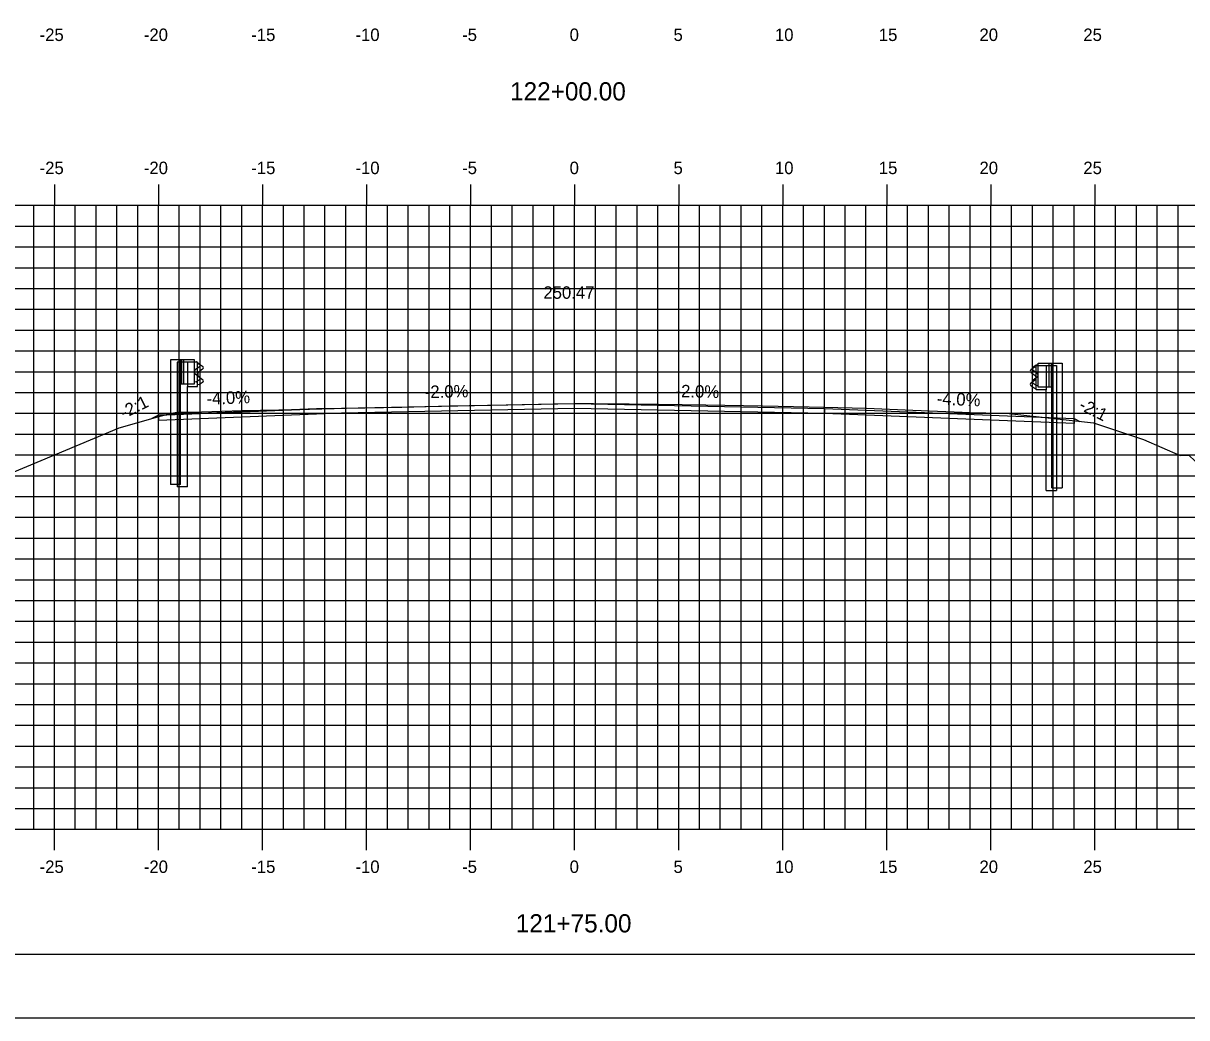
# Model space of a CAD drawing. Extents: x -22 to 1480, y -1511 to 8.
# Drawn here: x 1270.4 to 1326.4, y -1511.4 to -1463.6 of the extents above; entities that cross this region are included whole.
import ezdxf

# ---------------------------------------------------------------- set-up
doc = ezdxf.new("R2010")
doc.units = 0
for name, color, linetype in [('ANNOTATION', 7, 'Continuous'), ('BORDER', 7, 'Continuous'), ('D_Guardrail_Beam_Lt', 7, 'Continuous'), ('D_Guardrail_Beam_Rt', 7, 'Continuous'), ('D_Roadway_Centerline', 7, 'Continuous'), ('D_Roadway_Centerline_Text', 7, 'Continuous'), ('D_Roadway_Edge_Shoulder', 7, 'Continuous'), ('D_Roadway_Edge_TW', 7, 'Continuous'), ('D_Roadway_SlopeLines', 7, 'Continuous'), ('H_V ANNOTATION', 7, 'Continuous'), ('MAJOR', 7, 'Continuous'), ('MINOR', 7, 'Continuous'), ('PLOT BOUNDARY', 7, 'Continuous'), ('S_Guardrail_Beam', 7, 'Continuous'), ('S_Roadway_Centerline', 7, 'Continuous')]:
    doc.layers.add(name, color=color, linetype=linetype)

msp = doc.modelspace()

# ---------------------------------------------------------------- linework, layer by layer
at = {"layer": 'BORDER'}
msp.add_line((1221.939, -1508.331), (1381.939, -1508.331), dxfattribs=at)
at = {"layer": 'D_Guardrail_Beam_Lt'}
for p, q in [((1277.51, -1479.754), (1277.51, -1485.754)), ((1277.981, -1479.754), (1277.51, -1479.754)), ((1278.668, -1479.754), (1277.981, -1479.754)), ((1277.981, -1479.754), (1277.981, -1480.921)), ((1278.043, -1479.754), (1278.043, -1480.921)), ((1278.147, -1479.754), (1278.147, -1480.921)), ((1278.668, -1480.921), (1278.668, -1479.754)), ((1278.668, -1479.837), (1278.742, -1479.852)), ((1278.758, -1479.858), (1278.902, -1479.958)), ((1278.673, -1480.302), (1278.673, -1480.372)), ((1278.902, -1480.102), (1278.706, -1480.238)), ((1278.706, -1480.437), (1278.902, -1480.573)), ((1277.981, -1480.921), (1278.668, -1480.921)), ((1278.002, -1485.754), (1278.002, -1480.921)), ((1278.742, -1480.823), (1278.668, -1480.837)), ((1278.902, -1480.716), (1278.758, -1480.816)), ((1278.002, -1485.754), (1277.51, -1485.754))]:
    msp.add_line(p, q, dxfattribs=at)
for centre, major_axis, start_param, end_param in [((1278.734, -1479.892), (0.0417, 0), 0.959931, 1.376053), ((1278.851, -1480.03), (0.0877, 0), 5.323254, 7.243116), ((1278.752, -1480.302), (-0.0789, 0), 5.323254, 6.283185), ((1278.752, -1480.372), (-0.0789, 0), 6.283185, 7.243116), ((1278.851, -1480.644), (0.0877, 0), 5.323254, 7.243116), ((1278.734, -1480.782), (0.0417, 0), 4.907132, 5.323254)]:
    msp.add_ellipse(centre, major_axis=major_axis, ratio=0.995501, start_param=start_param, end_param=end_param, dxfattribs=at)
at = {"layer": 'D_Guardrail_Beam_Rt'}
for p, q in [((1319.12, -1480.018), (1318.977, -1480.118)), ((1319.21, -1479.997), (1319.136, -1480.012)), ((1319.21, -1479.914), (1319.897, -1479.914)), ((1319.21, -1481.081), (1319.21, -1479.914)), ((1319.731, -1479.914), (1319.731, -1481.081)), ((1319.835, -1479.914), (1319.835, -1481.081)), ((1319.897, -1479.914), (1320.368, -1479.914)), ((1319.897, -1479.914), (1319.897, -1481.081)), ((1320.368, -1479.914), (1320.368, -1485.914)), ((1318.977, -1480.262), (1319.172, -1480.398)), ((1319.172, -1480.597), (1318.977, -1480.733)), ((1319.206, -1480.462), (1319.206, -1480.532)), ((1318.977, -1480.876), (1319.12, -1480.976)), ((1319.136, -1480.983), (1319.21, -1480.997)), ((1319.897, -1481.081), (1319.21, -1481.081)), ((1319.877, -1485.914), (1319.877, -1481.081)), ((1319.877, -1485.914), (1320.368, -1485.914))]:
    msp.add_line(p, q, dxfattribs=at)
for centre, major_axis, start_param, end_param in [((1319.144, -1480.052), (-0.0417, 0), 4.907132, 5.323254), ((1319.027, -1480.19), (-0.0877, 0), 5.323254, 7.243116), ((1319.127, -1480.462), (0.0789, 0), 0, 0.959931), ((1319.127, -1480.532), (0.0789, 0), 5.323254, 6.283185), ((1319.027, -1480.804), (-0.0877, 0), 5.323254, 7.243116), ((1319.144, -1480.942), (-0.0417, 0), 0.959931, 1.376053)]:
    msp.add_ellipse(centre, major_axis=major_axis, ratio=0.995501, start_param=start_param, end_param=end_param, dxfattribs=at)
at = {"layer": 'D_Roadway_Centerline'}
msp.add_lwpolyline([(1276.623, -1482.575), (1276.939, -1482.417), (1278.939, -1482.337), (1284.939, -1482.097), (1296.939, -1481.857), (1308.939, -1482.097), (1318.939, -1482.497), (1320.939, -1482.577), (1321.222, -1482.718)], dxfattribs=at)
at = {"layer": 'D_Roadway_Edge_Shoulder'}
for points in [[(1284.939, -1482.097), (1278.939, -1482.337), (1278.939, -1482.337), (1276.939, -1482.417), (1276.939, -1482.667), (1278.939, -1482.587), (1278.939, -1482.587), (1284.939, -1482.347)], [(1308.939, -1482.097), (1318.939, -1482.497), (1318.939, -1482.497), (1320.939, -1482.577), (1320.939, -1482.827), (1318.939, -1482.747), (1318.939, -1482.747), (1308.939, -1482.347)]]:
    msp.add_lwpolyline(points, close=True, dxfattribs=at)
at = {"layer": 'D_Roadway_Edge_TW'}
msp.add_lwpolyline([(1284.939, -1482.347), (1284.939, -1482.097), (1296.939, -1481.857), (1308.939, -1482.097), (1308.939, -1482.347), (1296.939, -1482.107)], close=True, dxfattribs=at)
at = {"layer": 'D_Roadway_SlopeLines'}
for points in [[(1276.939, -1482.417), (1276.623, -1482.575)], [(1320.939, -1482.577), (1321.222, -1482.718)]]:
    msp.add_lwpolyline(points, dxfattribs=at)
at = {"layer": 'MAJOR'}
for p, q in [((1271.939, -1471.329), (1271.939, -1472.331)), ((1276.939, -1471.329), (1276.939, -1472.331)), ((1281.939, -1471.329), (1281.939, -1472.331)), ((1286.939, -1471.329), (1286.939, -1472.331)), ((1291.939, -1471.329), (1291.939, -1472.331)), ((1296.939, -1471.329), (1296.939, -1472.331)), ((1301.939, -1471.329), (1301.939, -1472.331)), ((1306.939, -1471.329), (1306.939, -1472.331)), ((1311.939, -1471.329), (1311.939, -1472.331)), ((1316.939, -1471.329), (1316.939, -1472.331)), ((1321.939, -1471.329), (1321.939, -1472.331)), ((1226.939, -1472.331), (1366.939, -1472.331)), ((1226.939, -1472.331), (1366.939, -1472.331)), ((1271.939, -1502.331), (1271.939, -1472.331)), ((1276.939, -1502.331), (1276.939, -1472.331)), ((1281.939, -1502.331), (1281.939, -1472.331)), ((1286.939, -1502.331), (1286.939, -1472.331)), ((1291.939, -1502.331), (1291.939, -1472.331)), ((1296.939, -1502.331), (1296.939, -1472.331)), ((1301.939, -1502.331), (1301.939, -1472.331)), ((1306.939, -1502.331), (1306.939, -1472.331)), ((1311.939, -1502.331), (1311.939, -1472.331)), ((1316.939, -1502.331), (1316.939, -1472.331)), ((1321.939, -1502.331), (1321.939, -1472.331)), ((1226.939, -1477.331), (1366.939, -1477.331)), ((1226.939, -1482.331), (1366.939, -1482.331)), ((1226.939, -1487.331), (1366.939, -1487.331)), ((1226.939, -1492.331), (1366.939, -1492.331)), ((1226.939, -1497.331), (1366.939, -1497.331)), ((1226.939, -1502.331), (1366.939, -1502.331)), ((1226.939, -1502.331), (1366.939, -1502.331)), ((1271.939, -1503.333), (1271.939, -1502.331)), ((1276.939, -1503.333), (1276.939, -1502.331)), ((1281.939, -1503.333), (1281.939, -1502.331)), ((1286.939, -1503.333), (1286.939, -1502.331)), ((1291.939, -1503.333), (1291.939, -1502.331)), ((1296.939, -1503.333), (1296.939, -1502.331)), ((1301.939, -1503.333), (1301.939, -1502.331)), ((1306.939, -1503.333), (1306.939, -1502.331)), ((1311.939, -1503.333), (1311.939, -1502.331)), ((1316.939, -1503.333), (1316.939, -1502.331)), ((1321.939, -1503.333), (1321.939, -1502.331))]:
    msp.add_line(p, q, dxfattribs=at)
at = {"layer": 'MINOR'}
for p, q in [((1270.939, -1502.331), (1270.939, -1472.331)), ((1272.939, -1502.331), (1272.939, -1472.331)), ((1273.939, -1502.331), (1273.939, -1472.331)), ((1274.939, -1502.331), (1274.939, -1472.331)), ((1275.939, -1502.331), (1275.939, -1472.331)), ((1277.939, -1502.331), (1277.939, -1472.331)), ((1278.939, -1502.331), (1278.939, -1472.331)), ((1279.939, -1502.331), (1279.939, -1472.331)), ((1280.939, -1502.331), (1280.939, -1472.331)), ((1282.939, -1502.331), (1282.939, -1472.331)), ((1283.939, -1502.331), (1283.939, -1472.331)), ((1284.939, -1502.331), (1284.939, -1472.331)), ((1285.939, -1502.331), (1285.939, -1472.331)), ((1287.939, -1502.331), (1287.939, -1472.331)), ((1288.939, -1502.331), (1288.939, -1472.331)), ((1289.939, -1502.331), (1289.939, -1472.331)), ((1290.939, -1502.331), (1290.939, -1472.331)), ((1292.939, -1502.331), (1292.939, -1472.331)), ((1293.939, -1502.331), (1293.939, -1472.331)), ((1294.939, -1502.331), (1294.939, -1472.331)), ((1295.939, -1502.331), (1295.939, -1472.331)), ((1297.939, -1502.331), (1297.939, -1472.331)), ((1298.939, -1502.331), (1298.939, -1472.331)), ((1299.939, -1502.331), (1299.939, -1472.331)), ((1300.939, -1502.331), (1300.939, -1472.331)), ((1302.939, -1502.331), (1302.939, -1472.331)), ((1303.939, -1502.331), (1303.939, -1472.331)), ((1304.939, -1502.331), (1304.939, -1472.331)), ((1305.939, -1502.331), (1305.939, -1472.331)), ((1307.939, -1502.331), (1307.939, -1472.331)), ((1308.939, -1502.331), (1308.939, -1472.331)), ((1309.939, -1502.331), (1309.939, -1472.331)), ((1310.939, -1502.331), (1310.939, -1472.331)), ((1312.939, -1502.331), (1312.939, -1472.331)), ((1313.939, -1502.331), (1313.939, -1472.331)), ((1314.939, -1502.331), (1314.939, -1472.331)), ((1315.939, -1502.331), (1315.939, -1472.331)), ((1317.939, -1502.331), (1317.939, -1472.331)), ((1318.939, -1502.331), (1318.939, -1472.331)), ((1319.939, -1502.331), (1319.939, -1472.331)), ((1320.939, -1502.331), (1320.939, -1472.331)), ((1322.939, -1502.331), (1322.939, -1472.331)), ((1323.939, -1502.331), (1323.939, -1472.331)), ((1324.939, -1502.331), (1324.939, -1472.331)), ((1325.939, -1502.331), (1325.939, -1472.331)), ((1226.939, -1473.331), (1366.939, -1473.331)), ((1226.939, -1474.331), (1366.939, -1474.331)), ((1226.939, -1475.331), (1366.939, -1475.331)), ((1226.939, -1476.331), (1366.939, -1476.331)), ((1226.939, -1478.331), (1366.939, -1478.331)), ((1226.939, -1479.331), (1366.939, -1479.331)), ((1226.939, -1480.331), (1366.939, -1480.331)), ((1226.939, -1481.331), (1366.939, -1481.331)), ((1226.939, -1483.331), (1366.939, -1483.331)), ((1226.939, -1484.331), (1366.939, -1484.331)), ((1226.939, -1485.331), (1366.939, -1485.331)), ((1226.939, -1486.331), (1366.939, -1486.331)), ((1226.939, -1488.331), (1366.939, -1488.331)), ((1226.939, -1489.331), (1366.939, -1489.331)), ((1226.939, -1490.331), (1366.939, -1490.331)), ((1226.939, -1491.331), (1366.939, -1491.331)), ((1226.939, -1493.331), (1366.939, -1493.331)), ((1226.939, -1494.331), (1366.939, -1494.331)), ((1226.939, -1495.331), (1366.939, -1495.331)), ((1226.939, -1496.331), (1366.939, -1496.331)), ((1226.939, -1498.331), (1366.939, -1498.331)), ((1226.939, -1499.331), (1366.939, -1499.331)), ((1226.939, -1500.331), (1366.939, -1500.331)), ((1226.939, -1501.331), (1366.939, -1501.331))]:
    msp.add_line(p, q, dxfattribs=at)
at = {"layer": 'PLOT BOUNDARY'}
msp.add_lwpolyline([(1213.846, -1511.39), (1383.846, -1511.39), (1383.846, -1401.39), (1213.846, -1401.39)], close=True, dxfattribs=at)
at = {"layer": 'S_Guardrail_Beam'}
for p, q in [((1277.836, -1479.871), (1277.836, -1485.871)), ((1278.328, -1479.871), (1277.836, -1479.871)), ((1278.817, -1479.871), (1278.328, -1479.871)), ((1278.328, -1479.871), (1278.328, -1481.038)), ((1278.817, -1481.038), (1278.817, -1479.871)), ((1278.817, -1479.944), (1278.899, -1479.958)), ((1278.916, -1479.965), (1279.059, -1480.065)), ((1319.117, -1480.037), (1319.607, -1480.037)), ((1319.117, -1481.203), (1319.117, -1480.037)), ((1319.607, -1480.037), (1320.098, -1480.037)), ((1319.607, -1480.037), (1319.607, -1481.203)), ((1320.098, -1480.037), (1320.098, -1486.037)), ((1278.83, -1480.409), (1278.83, -1480.5)), ((1279.059, -1480.208), (1278.864, -1480.345)), ((1278.864, -1480.564), (1279.059, -1480.701)), ((1319.018, -1480.131), (1318.875, -1480.231)), ((1318.875, -1480.374), (1319.07, -1480.51)), ((1319.117, -1480.11), (1319.035, -1480.124)), ((1319.104, -1480.574), (1319.104, -1480.666)), ((1278.328, -1485.871), (1278.328, -1481.038)), ((1278.328, -1481.038), (1278.817, -1481.038)), ((1278.899, -1480.951), (1278.817, -1480.965)), ((1279.059, -1480.844), (1278.916, -1480.944)), ((1319.07, -1480.73), (1318.875, -1480.866)), ((1318.875, -1481.009), (1319.018, -1481.109)), ((1319.035, -1481.116), (1319.117, -1481.13)), ((1319.607, -1481.203), (1319.117, -1481.203)), ((1319.607, -1486.037), (1319.607, -1481.203)), ((1278.328, -1485.871), (1277.836, -1485.871)), ((1319.607, -1486.037), (1320.098, -1486.037))]:
    msp.add_line(p, q, dxfattribs=at)
for centre, major_axis, start_param, end_param in [((1278.892, -1479.999), (0.0417, 0), 0.959931, 1.396263), ((1279.009, -1480.137), (0.0877, 0), 5.323254, 7.243116), ((1278.909, -1480.409), (-0.0789, 0), 5.323254, 6.283185), ((1278.909, -1480.5), (-0.0789, 0), 6.283185, 7.243116), ((1318.925, -1480.302), (-0.0877, 0), 5.323254, 7.243116), ((1319.042, -1480.165), (-0.0417, 0), 4.886922, 5.323254), ((1319.025, -1480.574), (0.0789, 0), 0, 0.959931), ((1278.892, -1480.91), (0.0417, 0), 4.886922, 5.323254), ((1279.009, -1480.772), (0.0877, 0), 5.323254, 7.243116), ((1318.925, -1480.938), (-0.0877, 0), 5.323254, 7.243116), ((1319.042, -1481.075), (-0.0417, 0), 0.959931, 1.396263), ((1319.025, -1480.666), (0.0789, 0), 5.323254, 6.283185)]:
    msp.add_ellipse(centre, major_axis=major_axis, ratio=0.995501, start_param=start_param, end_param=end_param, dxfattribs=at)
at = {"layer": 'S_Roadway_Centerline'}
for points in [[(1266.648, -1486.537), (1275.052, -1483.021), (1277.025, -1482.461), (1277.205, -1482.418), (1277.438, -1482.362), (1277.815, -1482.282), (1279.011, -1482.263), (1280.966, -1482.188), (1283.603, -1482.14), (1285.967, -1482.09), (1288.627, -1482.03), (1290.967, -1481.976), (1293.651, -1481.921), (1295.967, -1481.872), (1296.969, -1481.864), (1297.846, -1481.855), (1299.552, -1481.876), (1300.967, -1481.89), (1303.239, -1481.923), (1305.967, -1481.966), (1308.217, -1482.017), (1310.967, -1482.079), (1313.196, -1482.177), (1315.967, -1482.293), (1317.447, -1482.328), (1317.829, -1482.336), (1317.95, -1482.351), (1321.877, -1482.792), (1324.271, -1483.587), (1326.043, -1484.361)], [(1266.648, -1486.537), (1275.052, -1483.021), (1277.025, -1482.461), (1277.205, -1482.418), (1277.438, -1482.362), (1277.815, -1482.282), (1279.011, -1482.263), (1280.966, -1482.188), (1283.603, -1482.14), (1285.967, -1482.09), (1288.627, -1482.03), (1290.967, -1481.976), (1293.651, -1481.921), (1295.967, -1481.872), (1296.969, -1481.864), (1297.846, -1481.855), (1299.552, -1481.876), (1300.967, -1481.89), (1303.239, -1481.923), (1305.967, -1481.966), (1308.217, -1482.017), (1310.967, -1482.079), (1313.196, -1482.177), (1315.967, -1482.293), (1317.447, -1482.328), (1317.829, -1482.336)], [(1321.877, -1482.792), (1324.271, -1483.587), (1326.043, -1484.361), (1326.448, -1484.34), (1326.764, -1484.624), (1330.797, -1486.845), (1336.299, -1490.067), (1359.49, -1500.448), (1366.939, -1503.489)]]:
    msp.add_lwpolyline(points, dxfattribs=at)

# ---------------------------------------------------------------- texts
at = {"layer": 'ANNOTATION'}
for s, rotation, p in [('-2.0%', 1.1458, (1289.742, -1481.601)), ('-2.0%', 358.8542, (1301.782, -1481.554)), ('-2:1', 26.5651, (1275.279, -1482.604)), ('-4.0%', 2.2906, (1279.255, -1481.924)), ('-4.0%', 357.7094, (1314.335, -1481.912)), ('-2:1', 333.4349, (1321.123, -1482.115))]:
    msp.add_text(s, height=0.6, rotation=rotation, dxfattribs=at).set_placement(p)
at = {"layer": 'D_Roadway_Centerline'}
for s, p in [('C', (1296.934, -1481.857)), ('L', (1296.939, -1481.864))]:
    msp.add_text(s, height=0.0146, dxfattribs=at).set_placement(p)
at = {"layer": 'D_Roadway_Centerline_Text'}
msp.add_text('250.47', height=0.6, dxfattribs=at).set_placement((1295.435, -1476.825))
at = {"layer": 'H_V ANNOTATION'}
for s, height, p in [('-25', 0.6, (1271.225, -1464.431)), ('-20', 0.6, (1276.233, -1464.431)), ('-15', 0.6, (1281.396, -1464.431)), ('-10', 0.6, (1286.404, -1464.431)), ('-5', 0.6, (1291.53, -1464.431)), ('0', 0.6, (1296.698, -1464.431)), ('5', 0.6, (1301.69, -1464.431)), ('10', 0.6, (1306.564, -1464.431)), ('15', 0.6, (1311.556, -1464.431)), ('20', 0.6, (1316.393, -1464.431)), ('25', 0.6, (1321.385, -1464.431)), ('122+00.00', 0.875, (1293.834, -1467.288)), ('-25', 0.6, (1271.225, -1470.831)), ('-20', 0.6, (1276.233, -1470.831)), ('-15', 0.6, (1281.396, -1470.831)), ('-10', 0.6, (1286.404, -1470.831)), ('-5', 0.6, (1291.53, -1470.831)), ('0', 0.6, (1296.698, -1470.831)), ('5', 0.6, (1301.69, -1470.831)), ('10', 0.6, (1306.564, -1470.831)), ('15', 0.6, (1311.556, -1470.831)), ('20', 0.6, (1316.393, -1470.831)), ('25', 0.6, (1321.385, -1470.831)), ('-25', 0.6, (1271.225, -1504.431)), ('-20', 0.6, (1276.233, -1504.431)), ('-15', 0.6, (1281.396, -1504.431)), ('-10', 0.6, (1286.404, -1504.431)), ('-5', 0.6, (1291.53, -1504.431)), ('0', 0.6, (1296.698, -1504.431)), ('5', 0.6, (1301.69, -1504.431)), ('10', 0.6, (1306.564, -1504.431)), ('15', 0.6, (1311.556, -1504.431)), ('20', 0.6, (1316.393, -1504.431)), ('25', 0.6, (1321.385, -1504.431)), ('121+75.00', 0.875, (1294.107, -1507.288))]:
    msp.add_text(s, height=height, dxfattribs=at).set_placement(p)

doc.saveas('drawing.dxf')
